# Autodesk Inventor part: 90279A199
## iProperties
Created: 2011-01
Part Number: 90279A199
Document SubType Name: Modeling
Designer: Administrator
Density: 7.85 g/cm^3
Material: Steel
Mass: 2.76324 g
Surface Area: 6.63937 cm^2
Volume: 0.352006 cm^3
Translation Standard: STEP AP203
FileName: 90279A199.step
PreProcessor: SolidWorks 2006233
PostProcessor: Build: 236a, Release: 2009 RTM - Date: Fri 02/22/2008
Sent Units: Inches
Uncertainty: 1e-05
Author: Administrator
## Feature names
1. Base1
